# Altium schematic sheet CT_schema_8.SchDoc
size 252 x 159 mm
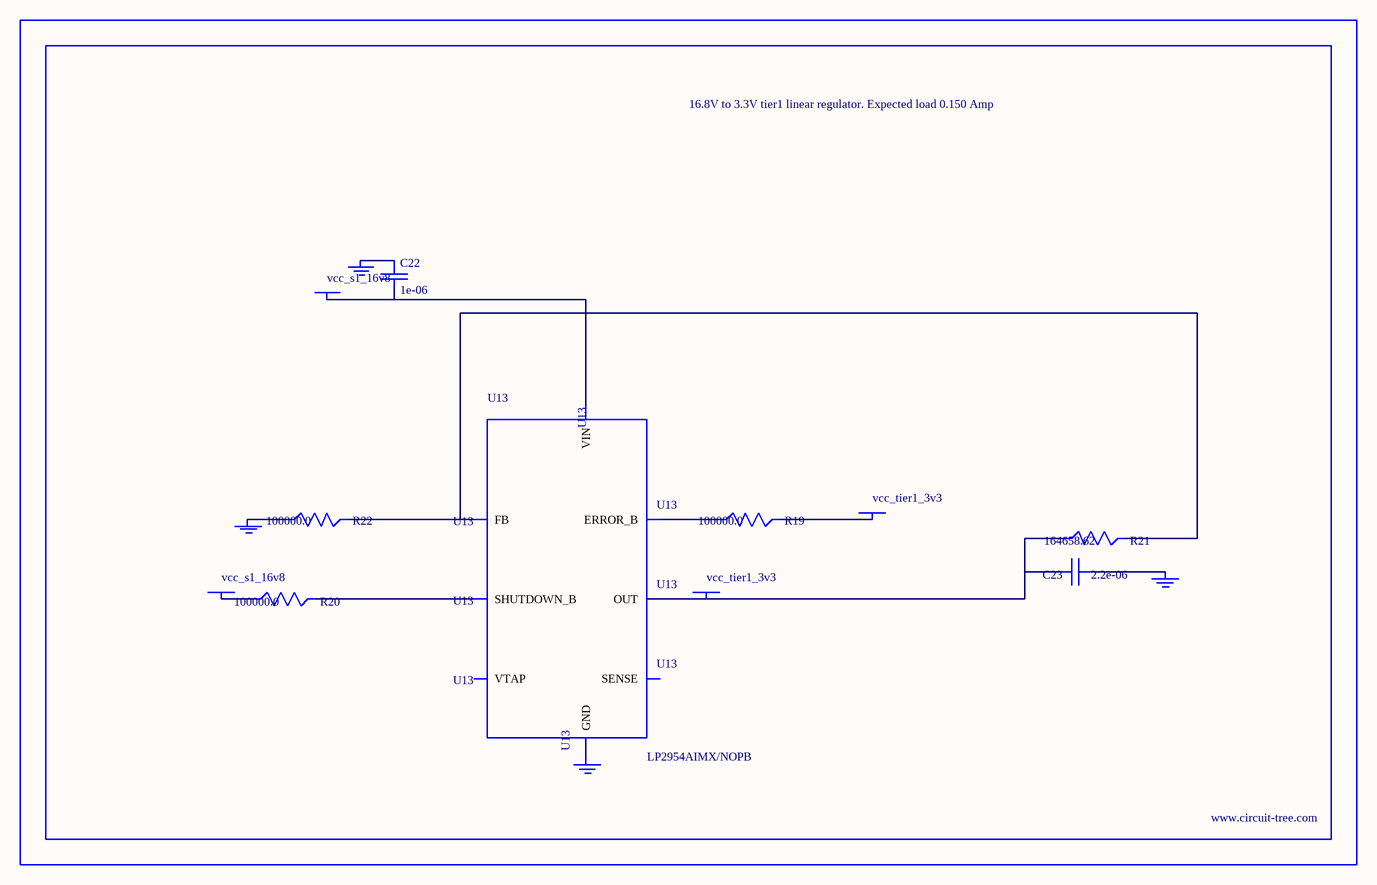
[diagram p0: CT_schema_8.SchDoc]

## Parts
BORDER7  (no value)
C22  1e-06  [EXV-9B]
C23  2.2e-06  [EXV-9B]
GND_INSTANCE_7_0  (no value)
GND_INSTANCE_7_1  (no value)
GND_INSTANCE_7_2  (no value)
GND_INSTANCE_7_3  (no value)
POWER_INSTANCE_7_0  vcc_s1_16v8
POWER_INSTANCE_7_1  vcc_tier1_3v3
POWER_INSTANCE_7_2  vcc_s1_16v8
POWER_INSTANCE_7_3  vcc_tier1_3v3
R19  100000.0  [R0603]
R20  100000.0  [R0603]
R21  164658.62  [R0603]
R22  100000.0  [R0603]
U13  LP2954AIMX/NOPB  [LP2954]

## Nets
NetC22_1: C22.1 GND_INSTANCE_7_2.0(GND)
NetC22_2: C22.2 POWER_INSTANCE_7_2.0(PWR) U13.8(VIN)
NetC23_1: C23.1 GND_INSTANCE_7_0.0(GND)
NetC23_2: C23.2 POWER_INSTANCE_7_3.0(PWR) R21.1 U13.1(OUT)
NetGND_INSTANCE_7_1_0: GND_INSTANCE_7_1.0(GND) R22.1
NetGND_INSTANCE_7_3_0: GND_INSTANCE_7_3.0(GND) U13.4(GND)
NetPOWER_INSTANCE_7_0_0: POWER_INSTANCE_7_0.0(PWR) R20.1
NetPOWER_INSTANCE_7_1_0: POWER_INSTANCE_7_1.0(PWR) R19.2
NetR19_1: R19.1 U13.5(ERROR_B)
NetR20_2: R20.2 U13.3(SHUTDOWN_B)
NetR21_2: R21.2 R22.2 U13.7(FB)

Not connected (* = marked no-connect by the designer): U13 2(SENSE) 6(VTAP)

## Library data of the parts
BORDER7 = BORDER_PAGE7
C22 = EDK105M050A9BAA
C23 = EDK225M050A9BAA
GND_INSTANCE_7_0-GND_INSTANCE_7_3 = GND
POWER_INSTANCE_7_0-POWER_INSTANCE_7_3 = PWR
R19 R20 R22 = RC0603JR-07100KL
R21 = R21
